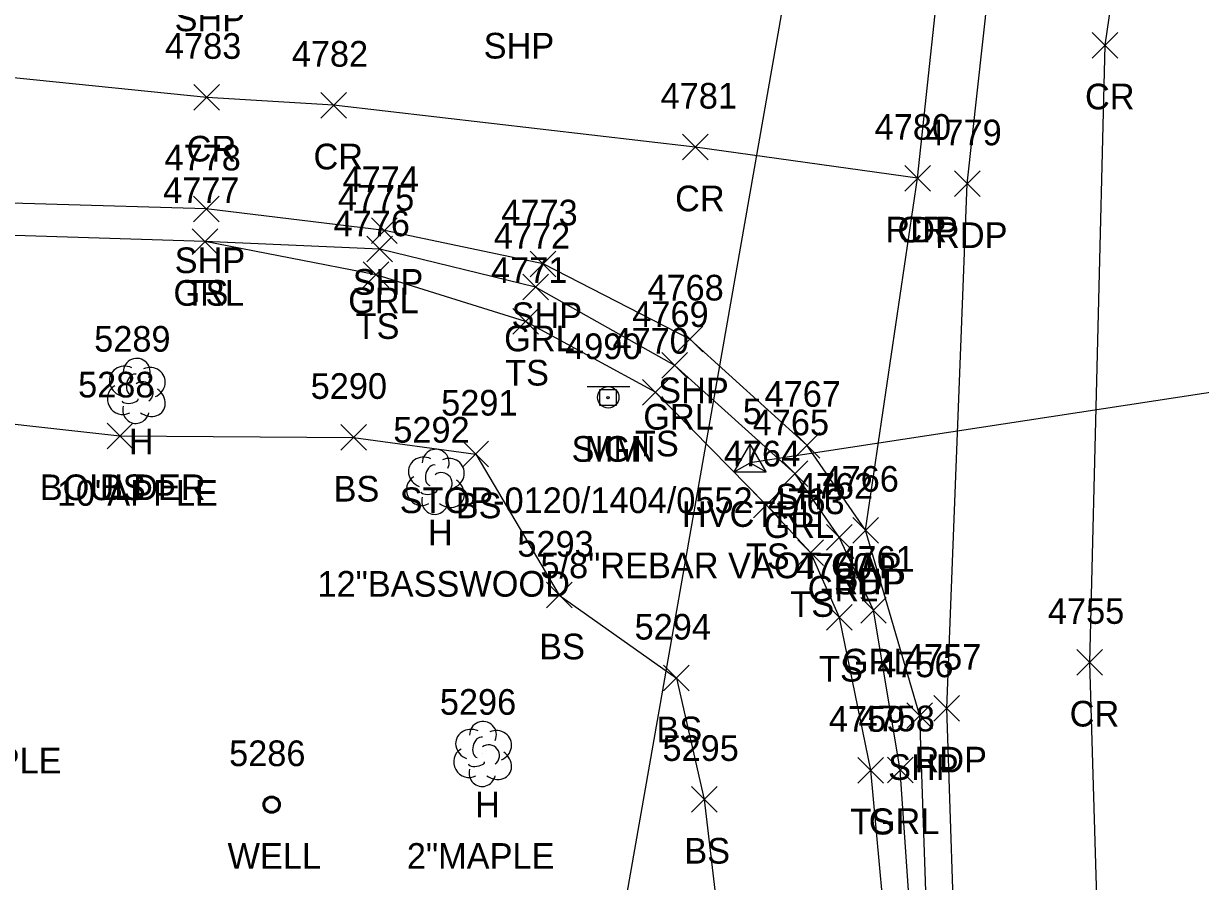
# Model space of a CAD drawing. Extents: x 1601151 to 1602912, y 499508 to 501770.
# Drawn here: x 1601373.9 to 1601465.7, y 501239.9 to 501306.7 of the extents above; entities that cross this region are included whole.
import ezdxf

# ---------------------------------------------------------------- set-up
doc = ezdxf.new("R2010")
doc.units = 0
for name, color, linetype in [('C_A', 7, 'Continuous'), ('C_C', 7, 'Continuous'), ('C_I', 7, 'Continuous'), ('CBT', 7, 'Continuous'), ('CPSM', 7, 'Continuous'), ('L_A', 7, 'Continuous'), ('L_C', 7, 'Continuous'), ('L_I', 7, 'Continuous'), ('L_TIC', 7, 'Continuous'), ('LELB', 7, 'Continuous'), ('LTD', 7, 'Continuous'), ('P_A', 7, 'Continuous'), ('P_I', 7, 'Continuous'), ('P_TIC', 7, 'Continuous'), ('PET', 7, 'Continuous'), ('PRC', 7, 'Continuous'), ('PSP', 7, 'Continuous'), ('R_A', 7, 'Continuous'), ('R_I', 7, 'Continuous'), ('R_TIC', 7, 'Continuous'), ('RGR', 7, 'Continuous'), ('S_A', 7, 'Continuous'), ('S_C', 7, 'Continuous'), ('S_I', 7, 'Continuous'), ('SRM', 7, 'Continuous'), ('SSGN', 7, 'Continuous'), ('U_A', 7, 'Continuous'), ('U_I', 7, 'Continuous'), ('UCO', 7, 'Continuous'), ('UWW', 7, 'Continuous')]:
    doc.layers.add(name, color=color, linetype=linetype)

msp = doc.modelspace()

# ---------------------------------------------------------------- linework, layer by layer
at = {"layer": 'CBT'}
msp.add_lwpolyline([(1601505.353, 501283.954), (1601430.559, 501272.528)], dxfattribs=at)
at = {"layer": 'CPSM'}
for p, q in [((1601429.309, 501271.807), (1601430.559, 501273.972)), ((1601431.809, 501271.807), (1601430.559, 501273.972)), ((1601430.559, 501272.528), (1601430.559, 501273.972)), ((1601429.309, 501271.807), (1601430.559, 501272.528)), ((1601429.309, 501271.807), (1601431.809, 501271.807)), ((1601430.559, 501272.528), (1601430.559, 501272.528)), ((1601430.559, 501272.528), (1601431.809, 501271.807))]:
    msp.add_line(p, q, dxfattribs=at)
at = {"layer": 'L_TIC'}
for points in [[(1601387.073, 501288.756), (1601389.073, 501290.756)], [(1601389.073, 501288.756), (1601387.073, 501290.756)], [(1601400.407, 501286.173), (1601402.407, 501288.173)], [(1601402.407, 501286.173), (1601400.407, 501288.173)], [(1601412.06, 501282.538), (1601414.06, 501284.538)], [(1601414.06, 501282.538), (1601412.06, 501284.538)], [(1601422.18, 501277.02), (1601424.18, 501279.02)], [(1601424.18, 501277.02), (1601422.18, 501279.02)], [(1601380.445, 501273.61), (1601382.445, 501275.61)], [(1601382.445, 501273.61), (1601380.445, 501275.61)], [(1601380.445, 501273.61), (1601382.445, 501275.61)], [(1601382.445, 501273.61), (1601380.445, 501275.61)], [(1601398.659, 501273.5), (1601400.659, 501275.5)], [(1601400.659, 501273.5), (1601398.659, 501275.5)], [(1601408.178, 501272.199), (1601410.178, 501274.199)], [(1601410.178, 501272.199), (1601408.178, 501274.199)], [(1601430.823, 501268.236), (1601432.823, 501270.236)], [(1601432.823, 501268.236), (1601430.823, 501270.236)], [(1601434.288, 501264.518), (1601436.288, 501266.518)], [(1601436.288, 501264.518), (1601434.288, 501266.518)], [(1601414.682, 501261.208), (1601416.682, 501263.208)], [(1601416.682, 501261.208), (1601414.682, 501263.208)], [(1601436.525, 501259.474), (1601438.525, 501261.474)], [(1601438.525, 501259.474), (1601436.525, 501261.474)], [(1601423.82, 501254.747), (1601425.82, 501256.747)], [(1601425.82, 501254.747), (1601423.82, 501256.747)], [(1601438.967, 501247.562), (1601440.967, 501249.562)], [(1601440.967, 501247.562), (1601438.967, 501249.562)], [(1601425.994, 501245.294), (1601427.994, 501247.294)], [(1601427.994, 501245.294), (1601425.994, 501247.294)]]:
    msp.add_lwpolyline(points, dxfattribs=at)
at = {"layer": 'LELB'}
for points in [[(1601519.45, 500871.015), (1601514.106, 500889.305), (1601500.792, 500936.504), (1601490.019, 500979.284), (1601479.001, 501021.428), (1601469.31, 501063.641), (1601460.331, 501100.011), (1601451.952, 501137.211), (1601445.853, 501173.31), (1601444.83, 501197.671), (1601441.57, 501231.326), (1601439.967, 501248.562), (1601437.525, 501260.474), (1601435.288, 501265.518), (1601431.823, 501269.236), (1601423.18, 501278.02), (1601413.06, 501283.538), (1601401.407, 501287.173), (1601388.073, 501289.756), (1601350.994, 501290.93), (1601302.639, 501293.089), (1601266.114, 501297.128)], [(1601265.967, 501291.231), (1601301.347, 501286.944), (1601350.829, 501278.015), (1601381.445, 501274.61), (1601399.659, 501274.5), (1601409.178, 501273.199), (1601415.682, 501262.208), (1601424.82, 501255.747), (1601426.994, 501246.294), (1601434.964, 501178.502), (1601436.145, 501158.977), (1601412.569, 501136.795), (1601410.789, 501093.147), (1601430.553, 501050.275)]]:
    msp.add_lwpolyline(points, dxfattribs=at)
at = {"layer": 'LTD'}
for p, q in [((1601382.708, 501278.175), (1601382.708, 501278.175)), ((1601382.708, 501278.175), (1601382.708, 501278.175)), ((1601406.015, 501271.09), (1601406.015, 501271.09)), ((1601406.015, 501271.09), (1601406.015, 501271.09)), ((1601409.698, 501249.889), (1601409.698, 501249.889)), ((1601409.698, 501249.889), (1601409.698, 501249.889))]:
    msp.add_line(p, q, dxfattribs=at)
for centre in [(1601382.755, 501279.609), (1601406.061, 501272.524), (1601409.745, 501251.323)]:
    msp.add_arc(centre, 1.047, 335.52715, 180.95627, dxfattribs=at)
for centre, major_axis, ratio, start_param, end_param in [((1601381.916, 501278.842), (1.21, -0.512), 0.895232, 1.570796, 4.712389), ((1601383.75, 501278.759), (-1.141, -0.483), 0.949671, 1.570796, 4.712389), ((1601382.5, 501278.634), (-0.208, -0.792), 0.645439, 3.141593, 6.283185), ((1601381.625, 501277.467), (0.584, -1.042), 0.959034, 3.141593, 6.283185), ((1601383.208, 501278.009), (-0.5, 0.667), 0.989748, 3.141593, 6.283185), ((1601383.708, 501277.342), (-1.09, 0.792), 0.841452, 1.570796, 4.712389), ((1601382.25, 501277.425), (-0.625, -0.083), 0.423636, 0, 3.141593), ((1601382.709, 501276.675), (0.265, 1.061), 0.942809, 1.570796, 4.712389), ((1601405.223, 501271.757), (1.21, -0.512), 0.895232, 1.570796, 4.712389), ((1601407.056, 501271.674), (-1.141, -0.483), 0.949671, 1.570796, 4.712389), ((1601405.806, 501271.548), (-0.208, -0.792), 0.645439, 3.141593, 6.283185), ((1601406.515, 501270.924), (-0.5, 0.667), 0.989748, 3.141593, 6.283185), ((1601404.931, 501270.382), (0.584, -1.042), 0.959034, 3.141593, 6.283185), ((1601407.015, 501270.257), (-1.09, 0.792), 0.841452, 1.570796, 4.712389), ((1601405.556, 501270.34), (-0.625, -0.083), 0.423636, 0, 3.141593), ((1601406.015, 501269.59), (0.265, 1.061), 0.942809, 1.570796, 4.712389), ((1601408.906, 501250.555), (1.21, -0.512), 0.895232, 1.570796, 4.712389), ((1601410.74, 501250.472), (-1.141, -0.483), 0.949671, 1.570796, 4.712389), ((1601409.49, 501250.347), (-0.208, -0.792), 0.645439, 3.141593, 6.283185), ((1601410.198, 501249.722), (-0.5, 0.667), 0.989748, 3.141593, 6.283185), ((1601408.615, 501249.18), (0.584, -1.042), 0.959034, 3.141593, 6.283185), ((1601410.698, 501249.056), (-1.09, 0.792), 0.841452, 1.570796, 4.712389), ((1601409.24, 501249.139), (-0.625, -0.083), 0.423636, 0, 3.141593), ((1601409.699, 501248.389), (0.265, 1.061), 0.942809, 1.570796, 4.712389)]:
    msp.add_ellipse(centre, major_axis=major_axis, ratio=ratio, start_param=start_param, end_param=end_param, dxfattribs=at)
at = {"layer": 'P_TIC'}
for points in [[(1601457.232, 501304.055), (1601459.232, 501306.055)], [(1601459.232, 501304.055), (1601457.232, 501306.055)], [(1601387.217, 501299.992), (1601389.217, 501301.992)], [(1601389.217, 501299.992), (1601387.217, 501301.992)], [(1601397.1, 501299.38), (1601399.1, 501301.38)], [(1601399.1, 501299.38), (1601397.1, 501301.38)], [(1601425.283, 501296.115), (1601427.283, 501298.115)], [(1601427.283, 501296.115), (1601425.283, 501298.115)], [(1601442.619, 501293.686), (1601444.619, 501295.686)], [(1601444.619, 501293.686), (1601442.619, 501295.686)], [(1601442.619, 501293.686), (1601444.619, 501295.686)], [(1601444.619, 501293.686), (1601442.619, 501295.686)], [(1601446.493, 501293.254), (1601448.493, 501295.254)], [(1601448.493, 501293.254), (1601446.493, 501295.254)], [(1601387.178, 501291.297), (1601389.178, 501293.297)], [(1601389.178, 501291.297), (1601387.178, 501293.297)], [(1601401.059, 501289.613), (1601403.059, 501291.613)], [(1601403.059, 501289.613), (1601401.059, 501291.613)], [(1601413.434, 501287.016), (1601415.434, 501289.016)], [(1601415.434, 501287.016), (1601413.434, 501289.016)], [(1601424.866, 501281.164), (1601426.866, 501283.164)], [(1601426.866, 501281.164), (1601424.866, 501283.164)], [(1601433.996, 501272.885), (1601435.996, 501274.885)], [(1601435.996, 501272.885), (1601433.996, 501274.885)], [(1601438.569, 501266.268), (1601440.569, 501268.268)], [(1601440.569, 501266.268), (1601438.569, 501268.268)], [(1601438.569, 501266.268), (1601440.569, 501268.268)], [(1601440.569, 501266.268), (1601438.569, 501268.268)], [(1601456.034, 501255.973), (1601458.034, 501257.973)], [(1601458.034, 501255.973), (1601456.034, 501257.973)], [(1601444.888, 501252.394), (1601446.888, 501254.394)], [(1601446.888, 501252.394), (1601444.888, 501254.394)], [(1601442.787, 501251.816), (1601444.787, 501253.816)], [(1601444.787, 501251.816), (1601442.787, 501253.816)]]:
    msp.add_lwpolyline(points, dxfattribs=at)
at = {"layer": 'PET'}
for points in [[(1601523.483, 500870.901), (1601505.835, 500938.639), (1601494.516, 500981.09), (1601483.993, 501022.882), (1601473.436, 501065.013), (1601465.152, 501101.359), (1601457.991, 501138.154), (1601451.804, 501174.879), (1601449.078, 501198.013), (1601446.661, 501230.716), (1601445.888, 501253.394), (1601447.493, 501294.254), (1601451.947, 501334.775), (1601458.706, 501377.25), (1601475.949, 501468.235), (1601495.788, 501558.679), (1601503.764, 501593.609), (1601511.667, 501629.007)], [(1601439.569, 501267.268), (1601443.619, 501294.686), (1601447.663, 501332.399)]]:
    msp.add_lwpolyline(points, dxfattribs=at)
at = {"layer": 'PRC'}
for points in [[(1601533.301, 500873.429), (1601528.203, 500892.927), (1601515.881, 500940.69), (1601516.086, 500940.413), (1601505.083, 500982.796), (1601494.066, 501025.459), (1601483.894, 501067.42), (1601475.626, 501103.842), (1601468.616, 501140.875), (1601462.895, 501176.52), (1601460.41, 501198.758), (1601457.835, 501229.924), (1601457.034, 501256.973), (1601458.232, 501305.055), (1601463.89, 501343.749), (1601469.525, 501375.722), (1601487.672, 501465.727), (1601498.93, 501516.839), (1601507.235, 501554.653), (1601515.351, 501591.128), (1601523.432, 501627.297), (1601533.113, 501671.567)], [(1601443.619, 501294.686), (1601426.283, 501297.115), (1601398.1, 501300.38), (1601388.217, 501300.992), (1601349.888, 501304.869), (1601302.818, 501306.543), (1601267.739, 501309.028)]]:
    msp.add_lwpolyline(points, dxfattribs=at)
at = {"layer": 'PSP'}
msp.add_lwpolyline([(1601522.474, 500870.61), (1601521.439, 500871.557), (1601516.681, 500890.315), (1601504.629, 500938.047), (1601493.734, 500980.105), (1601482.813, 501022.433), (1601472.391, 501064.7), (1601463.732, 501101.178), (1601456.463, 501137.785), (1601450.781, 501174.537), (1601447.494, 501198.124), (1601444.544, 501230.817), (1601443.787, 501252.816), (1601439.569, 501267.268), (1601434.996, 501273.885), (1601425.866, 501282.164), (1601414.434, 501288.016), (1601402.059, 501290.613), (1601388.178, 501292.297), (1601350.65, 501293.394), (1601302.631, 501296.391), (1601266.655, 501300.033)], dxfattribs=at)
at = {"layer": 'R_TIC'}
for points in [[(1601387.073, 501288.756), (1601389.073, 501290.756)], [(1601389.073, 501288.756), (1601387.073, 501290.756)], [(1601400.696, 501288.169), (1601402.696, 501290.169)], [(1601402.696, 501288.169), (1601400.696, 501290.169)], [(1601412.846, 501285.207), (1601414.846, 501287.207)], [(1601414.846, 501285.207), (1601412.846, 501287.207)], [(1601423.696, 501279.104), (1601425.696, 501281.104)], [(1601425.696, 501279.104), (1601423.696, 501281.104)], [(1601433.074, 501270.664), (1601435.074, 501272.664)], [(1601435.074, 501270.664), (1601433.074, 501272.664)], [(1601436.509, 501265.718), (1601438.509, 501267.718)], [(1601438.509, 501265.718), (1601436.509, 501267.718)], [(1601439.181, 501260.029), (1601441.181, 501262.029)], [(1601441.181, 501260.029), (1601439.181, 501262.029)], [(1601441.272, 501247.597), (1601443.272, 501249.597)], [(1601443.272, 501247.597), (1601441.272, 501249.597)]]:
    msp.add_lwpolyline(points, dxfattribs=at)
at = {"layer": 'RGR'}
msp.add_lwpolyline([(1601521.194, 500871.519), (1601516.168, 500890.132), (1601503.522, 500937.626), (1601493.244, 500980.032), (1601482.37, 501022.092), (1601471.561, 501064.484), (1601463.235, 501100.712), (1601455.926, 501137.469), (1601449.863, 501174.239), (1601446.894, 501198.084), (1601443.458, 501231.306), (1601442.272, 501248.597), (1601440.181, 501261.029), (1601437.509, 501266.718), (1601434.074, 501271.664), (1601424.696, 501280.104), (1601413.846, 501286.207), (1601401.696, 501289.169), (1601388.073, 501289.756)], dxfattribs=at)
at = {"layer": 'SRM'}
msp.add_lwpolyline([(1601418.863, 501278.224), (1601420.113, 501278.224), (1601420.113, 501276.974), (1601418.863, 501276.974)], close=True, dxfattribs=at)
msp.add_circle((1601419.488, 501277.599), 0.0833, dxfattribs=at)
at = {"layer": 'SSGN'}
for p, q in [((1601417.861, 501278.453), (1601421.194, 501278.453)), ((1601419.508, 501277.619), (1601419.508, 501277.619))]:
    msp.add_line(p, q, dxfattribs=at)
msp.add_circle((1601419.508, 501277.619), 0.833, dxfattribs=at)
at = {"layer": 'UCO'}
msp.add_lwpolyline([(1601766.645, 501489.445), (1601471.02, 501503.898), (1601438.705, 501339.971), (1601411.283, 501184.01), (1601489.931, 500928.889)], dxfattribs=at)
at = {"layer": 'UWW'}
for radius in [0.667, 0.625, 0.583, 0.542]:
    msp.add_circle((1601393.271, 501245.888), radius, dxfattribs=at)

# ---------------------------------------------------------------- texts
at = {"layer": 'C_A'}
msp.add_text('HVCTRL', height=2, dxfattribs=at).set_placement((1601425.252, 501267.528))
at = {"layer": 'C_C'}
msp.add_text('5/8"REBAR VAOT CAP', height=2, dxfattribs=at).set_placement((1601414.221, 501263.528))
at = {"layer": 'C_I'}
msp.add_text('5', height=2, dxfattribs=at).set_placement((1601429.992, 501275.528))
at = {"layer": 'L_A'}
for s, p in [('TS', (1601386.483, 501284.756)), ('TS', (1601399.817, 501282.173)), ('TS', (1601411.47, 501278.538)), ('H', (1601382.141, 501273.175)), ('TS', (1601421.59, 501273.02)), ('BOULDER', (1601375.201, 501269.61)), ('BS', (1601379.886, 501269.61)), ('BS', (1601398.1, 501269.5)), ('BS', (1601407.619, 501268.199)), ('H', (1601405.448, 501266.09)), ('TS', (1601430.232, 501264.236)), ('TS', (1601433.698, 501260.518)), ('BS', (1601414.123, 501257.208)), ('TS', (1601435.934, 501255.474)), ('BS', (1601423.261, 501250.747)), ('H', (1601409.131, 501244.889)), ('TS', (1601438.376, 501243.562)), ('BS', (1601425.435, 501241.294))]:
    msp.add_text(s, height=2, dxfattribs=at).set_placement(p)
at = {"layer": 'L_C'}
for s, p in [('10"APPLE', (1601376.535, 501269.175)), ('12"BASSWOOD', (1601396.842, 501262.09)), ('14"MAPLE', (1601363.905, 501248.315)), ('2"MAPLE', (1601403.809, 501240.889))]:
    msp.add_text(s, height=2, dxfattribs=at).set_placement(p)
at = {"layer": 'L_I'}
for s, p in [('4777', (1601384.813, 501292.756)), ('4776', (1601398.093, 501290.173)), ('4771', (1601410.368, 501286.538)), ('5289', (1601379.441, 501281.175)), ('4770', (1601419.834, 501281.02)), ('5288', (1601378.186, 501277.61)), ('5288', (1601378.186, 501277.61)), ('5290', (1601396.313, 501277.5)), ('5291', (1601406.485, 501276.199)), ('5292', (1601402.755, 501274.09)), ('4764', (1601428.516, 501272.236)), ('4763', (1601431.981, 501268.518)), ('5293', (1601412.422, 501265.208)), ('4760', (1601434.131, 501263.474)), ('5294', (1601421.56, 501258.747)), ('5296', (1601406.383, 501252.889)), ('4759', (1601436.699, 501251.562)), ('5295', (1601423.734, 501249.294))]:
    msp.add_text(s, height=2, dxfattribs=at).set_placement(p)
at = {"layer": 'P_A'}
for s, p in [('SHP', (1601385.707, 501306.145)), ('SHP', (1601409.797, 501304.016)), ('CR', (1601456.665, 501300.055)), ('CR', (1601386.65, 501295.992)), ('CR', (1601396.533, 501295.38)), ('CR', (1601424.717, 501292.115)), ('RDP', (1601441.107, 501289.686)), ('CR', (1601442.052, 501289.686)), ('RDP', (1601444.981, 501289.254)), ('SHP', (1601385.714, 501287.297)), ('SHP', (1601399.595, 501285.613)), ('SHP', (1601411.97, 501283.016)), ('SHP', (1601423.402, 501277.164)), ('SHP', (1601432.532, 501268.885)), ('SHP', (1601437.105, 501262.268)), ('RDP', (1601437.057, 501262.268)), ('CR', (1601455.468, 501251.973)), ('SHP', (1601441.322, 501247.816)), ('RDP', (1601443.376, 501248.394))]:
    msp.add_text(s, height=2, dxfattribs=at).set_placement(p)
at = {"layer": 'P_I'}
for s, p in [('4783', (1601384.958, 501303.992)), ('4782', (1601394.84, 501303.38)), ('4781', (1601423.591, 501300.115)), ('4780', (1601440.273, 501297.686)), ('4780', (1601440.273, 501297.686)), ('4779', (1601444.225, 501297.254)), ('4778', (1601384.919, 501295.297)), ('4774', (1601398.8, 501293.613)), ('4773', (1601411.175, 501291.016)), ('4768', (1601422.559, 501285.164)), ('4767', (1601431.689, 501276.885)), ('4766', (1601436.207, 501270.268)), ('4766', (1601436.207, 501270.268)), ('4755', (1601453.775, 501259.973)), ('4757', (1601442.628, 501256.394)), ('4756', (1601440.472, 501255.816))]:
    msp.add_text(s, height=2, dxfattribs=at).set_placement(p)
at = {"layer": 'R_A'}
for p in [(1601385.616, 501284.756), (1601399.239, 501284.169), (1601411.39, 501281.207), (1601422.239, 501275.104), (1601431.617, 501266.664), (1601435.052, 501261.718), (1601437.724, 501256.029), (1601439.815, 501243.597)]:
    msp.add_text('GRL', height=2, dxfattribs=at).set_placement(p)
at = {"layer": 'R_I'}
for s, p in [('4777', (1601384.813, 501292.756)), ('4775', (1601398.436, 501292.169)), ('4772', (1601410.587, 501289.207)), ('4769', (1601421.381, 501283.104)), ('4765', (1601430.767, 501274.664)), ('4762', (1601434.202, 501269.718)), ('4761', (1601437.441, 501264.029)), ('4758', (1601439.012, 501251.597))]:
    msp.add_text(s, height=2, dxfattribs=at).set_placement(p)
at = {"layer": 'S_A'}
for s, p in [('SIGN', (1601416.646, 501272.599)), ('MM', (1601417.677, 501272.599))]:
    msp.add_text(s, height=2, dxfattribs=at).set_placement(p)
at = {"layer": 'S_C'}
msp.add_text('STOP-0120/1404/0552', height=2, dxfattribs=at).set_placement((1601403.252, 501268.599))
at = {"layer": 'S_I'}
msp.add_text('4990', height=2, dxfattribs=at).set_placement((1601416.142, 501280.599))
msp.add_text('4990', height=2, dxfattribs=at).set_placement((1601416.142, 501280.599))
at = {"layer": 'U_A'}
msp.add_text('WELL', height=2, dxfattribs=at).set_placement((1601389.838, 501240.888))
at = {"layer": 'U_I'}
msp.add_text('5286', height=2, dxfattribs=at).set_placement((1601389.956, 501248.888))

doc.saveas('drawing.dxf')
